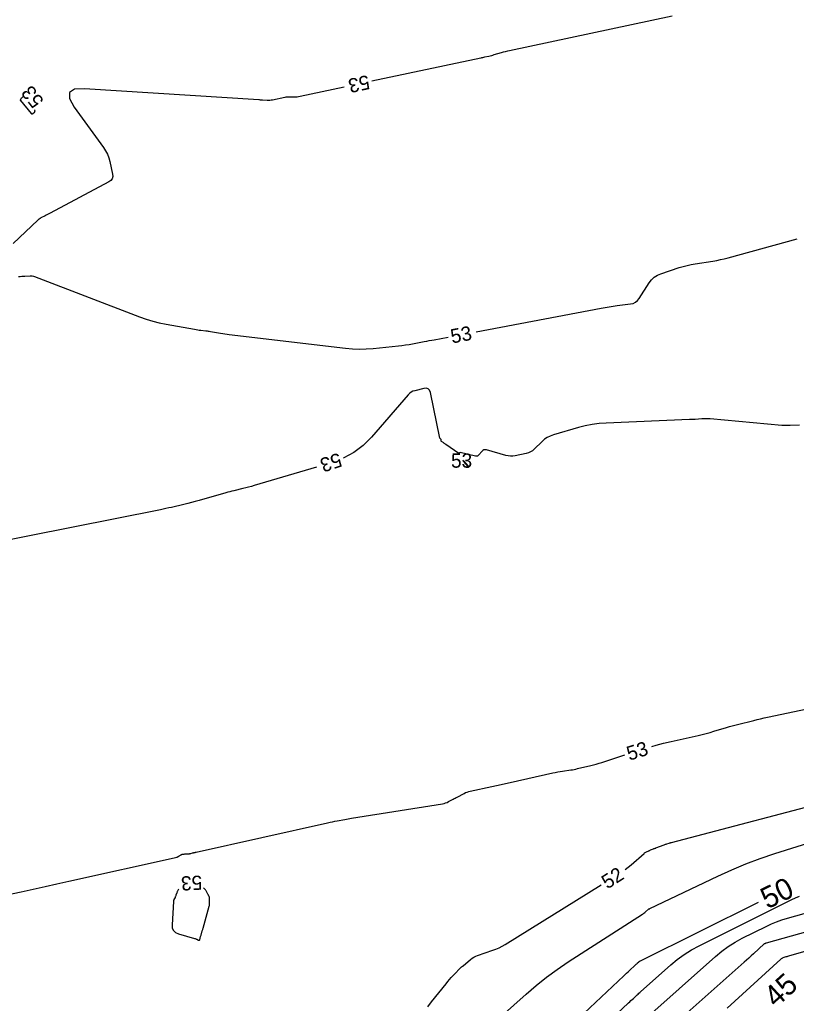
# Model space of a CAD drawing. Extents: x 2384780 to 2405861, y 547869 to 573706.
# Drawn here: x 2389896.7 to 2390006.1, y 552348.1 to 552486.4 of the extents above; entities that cross this region are included whole.
import ezdxf

# ---------------------------------------------------------------- set-up
doc = ezdxf.new("R2010")
doc.units = 0
doc.layers.add('Old_Level_60', color=7, linetype='Continuous')
doc.layers.add('Old_Level_61', color=7, linetype='Continuous')

msp = doc.modelspace()

# ---------------------------------------------------------------- linework, layer by layer
at = {"layer": 'Old_Level_60'}
for points in [[(2389988.59725, 552486.9505), (2389965.6925, 552482.06725), (2389965.39375, 552482.0005), (2389965.09625, 552481.9285), (2389964.8005, 552481.85075), (2389964.50575, 552481.76775), (2389963.5, 552481.47375), (2389963.317, 552481.42175), (2389963.13275, 552481.37275), (2389962.948, 552481.327), (2389962.7625, 552481.284), (2389962.155, 552481.149), (2389962.02475, 552481.12025), (2389961.8945, 552481.09175), (2389961.76425, 552481.0635), (2389961.63375, 552481.03575), (2389946.313, 552477.773)], [(2389942.40075, 552476.93975), (2389936.20025, 552475.61925), (2389935.99075, 552475.581), (2389935.78, 552475.5555), (2389935.568, 552475.5425), (2389935.355, 552475.54225), (2389934.657, 552475.56175), (2389934.508, 552475.56125), (2389934.3595, 552475.55225), (2389934.212, 552475.53425), (2389934.06525, 552475.5075), (2389932.32925, 552475.137), (2389932.1385, 552475.103), (2389931.94675, 552475.082), (2389931.75425, 552475.07425), (2389931.5605, 552475.0795), (2389930.926, 552475.11875), (2389930.79025, 552475.127), (2389930.65425, 552475.13575), (2389930.51825, 552475.14425), (2389930.3825, 552475.153), (2389905.84725, 552476.73475), (2389904.4555, 552476.65675), (2389903.75375, 552476.19875), (2389903.742, 552475.361), (2389904.42025, 552474.14325), (2389908.5465, 552468.46775), (2389908.845, 552468.00925), (2389909.0915, 552467.52775), (2389909.28575, 552467.02275), (2389909.428, 552466.4945), (2389909.807, 552464.73075), (2389909.83525, 552464.37725), (2389909.758, 552464.07325), (2389909.575, 552463.81825), (2389909.28625, 552463.61275), (2389901.01925, 552459.23), (2389900.84175, 552459.136), (2389900.6645, 552459.042), (2389900.487, 552458.948), (2389900.30975, 552458.854), (2389899.73025, 552458.54675), (2389899.60875, 552458.477), (2389899.49275, 552458.39975), (2389899.38225, 552458.31475), (2389899.27725, 552458.22225), (2389895.83, 552454.972)], [(2389897.25875, 552475.6915), (2389896.9425, 552475.366), (2389896.93175, 552475.354), (2389896.92225, 552475.341), (2389896.91375, 552475.327), (2389896.90675, 552475.3125), (2389896.88525, 552475.26325), (2389896.88075, 552475.25275), (2389896.876, 552475.24225), (2389896.87125, 552475.232), (2389896.86625, 552475.2215), (2389896.82675, 552475.139), (2389896.821, 552475.1215), (2389896.82025, 552475.105), (2389896.825, 552475.08875), (2389896.835, 552475.0735), (2389898.35175, 552473.256), (2389898.4125, 552473.20125), (2389898.4755, 552473.1805), (2389898.54025, 552473.19375), (2389898.60725, 552473.24125), (2389898.8285, 552473.452), (2389898.86825, 552473.4995), (2389898.8925, 552473.55175), (2389898.90125, 552473.6085), (2389898.8945, 552473.67025), (2389898.87625, 552473.7505)], [(2389897.30775, 552475.7415), (2389897.25875, 552475.6915)], [(2389960.992, 552442.54), (2389978.57725, 552445.87125), (2389979.1425, 552445.9735), (2389979.70925, 552446.06625), (2389980.27725, 552446.14925), (2389980.847, 552446.223), (2389982.71, 552446.44825), (2389983.0865, 552446.53275), (2389983.4175, 552446.68975), (2389983.703, 552446.91925), (2389983.94325, 552447.22125), (2389985.347, 552449.40675), (2389985.67625, 552449.8385), (2389986.06225, 552450.1975), (2389986.50475, 552450.4835), (2389987.00425, 552450.69675), (2389989.5745, 552451.557), (2389990.12825, 552451.72925), (2389990.68775, 552451.8775), (2389991.253, 552452.00175), (2389991.824, 552452.102), (2389994.33075, 552452.487), (2389994.86625, 552452.577), (2389995.3985, 552452.68275), (2389995.92725, 552452.8035), (2389996.453, 552452.94), (2390006.18225, 552455.61525)], [(2389896.57675, 552450.29525), (2389896.7995, 552450.32475), (2389897.02275, 552450.34825), (2389897.2465, 552450.36575), (2389897.47075, 552450.37775), (2389898.20425, 552450.4065), (2389898.36025, 552450.40475), (2389898.5135, 552450.3875), (2389898.66425, 552450.35475), (2389898.8125, 552450.30625), (2389913.62475, 552444.636), (2389914.537, 552444.31125), (2389915.4615, 552444.03075), (2389916.39825, 552443.79475), (2389917.34725, 552443.60275), (2389921.36825, 552442.888), (2389921.587, 552442.85075), (2389921.806, 552442.8165), (2389922.0255, 552442.785), (2389922.2455, 552442.75675), (2389922.965, 552442.669), (2389923.119, 552442.64925), (2389923.27275, 552442.628), (2389923.42625, 552442.60475), (2389923.5795, 552442.58), (2389925.00975, 552442.34075), (2389925.3165, 552442.2915), (2389925.624, 552442.24575), (2389925.93175, 552442.2035), (2389926.24, 552442.16525), (2389942.59225, 552440.23175), (2389943.56775, 552440.143), (2389944.54375, 552440.108), (2389945.52025, 552440.12625), (2389946.49725, 552440.19825), (2389950.045, 552440.556), (2389950.5505, 552440.6125), (2389951.05425, 552440.68), (2389951.5565, 552440.75825), (2389952.057, 552440.8475), (2389953.69, 552441.157), (2389954.04, 552441.22325), (2389954.38975, 552441.2895), (2389954.73975, 552441.35575), (2389955.08975, 552441.422), (2389957.06175, 552441.7955)], [(2390006.52175, 552429.3855), (2390005.18, 552429.3355), (2390004.89275, 552429.3295), (2390004.6055, 552429.33225), (2390004.31875, 552429.34425), (2390004.032, 552429.36525), (2389993.932, 552430.266), (2389993.6435, 552430.28625), (2389993.355, 552430.295), (2389993.06625, 552430.2925), (2389992.7775, 552430.279), (2389991.83375, 552430.21575), (2389991.6315, 552430.203), (2389991.42925, 552430.1915), (2389991.22675, 552430.18125), (2389991.02425, 552430.17225), (2389979.28525, 552429.69225), (2389978.299, 552429.62225), (2389977.32275, 552429.493), (2389976.35575, 552429.3045), (2389975.39875, 552429.057), (2389971.8675, 552428.02975), (2389971.42575, 552427.87175), (2389971.013, 552427.66425), (2389970.6295, 552427.4065), (2389970.275, 552427.099), (2389969.16525, 552426.01275), (2389968.9165, 552425.80075), (2389968.6455, 552425.6305), (2389968.3525, 552425.502), (2389968.03725, 552425.415), (2389966.4905, 552425.10175), (2389966.15975, 552425.05425), (2389965.8305, 552425.04675), (2389965.50275, 552425.07875), (2389965.1765, 552425.15025), (2389962.455, 552425.9145), (2389962.26825, 552425.943), (2389962.0975, 552425.919), (2389961.94325, 552425.84225), (2389961.80525, 552425.713), (2389961.381, 552425.20525), (2389961.28425, 552425.11375), (2389961.1755, 552425.05725), (2389961.055, 552425.03575), (2389960.9225, 552425.049), (2389958.75425, 552425.53125), (2389958.72875, 552425.5335), (2389958.70625, 552425.52875), (2389958.68625, 552425.51675), (2389958.66925, 552425.4975), (2389958.6185, 552425.423), (2389958.607, 552425.4105), (2389958.59425, 552425.4045), (2389958.58, 552425.4055), (2389958.56475, 552425.413), (2389956.745, 552426.66975), (2389956.6655, 552426.72475), (2389956.58625, 552426.78), (2389956.507, 552426.83525), (2389956.42775, 552426.89075), (2389956.12275, 552427.105), (2389956.0945, 552427.12975), (2389956.074, 552427.1585), (2389956.0615, 552427.1915), (2389956.0565, 552427.2285), (2389956.05325, 552427.35725), (2389956.05, 552427.383), (2389956.0415, 552427.40625), (2389956.028, 552427.427), (2389956.0095, 552427.44525), (2389955.94025, 552427.50025), (2389955.92675, 552427.513), (2389955.916, 552427.52725), (2389955.908, 552427.54325), (2389955.90275, 552427.561), (2389954.56425, 552433.977), (2389954.4435, 552434.31), (2389954.2455, 552434.5195), (2389953.97025, 552434.60575), (2389953.618, 552434.5685), (2389952.3415, 552434.24575), (2389952.079, 552434.1585), (2389951.83875, 552434.03525), (2389951.62075, 552433.87625), (2389951.42475, 552433.681), (2389946.26075, 552427.726)], [(2389946.26075, 552427.726), (2389945.09025, 552426.54875), (2389943.79175, 552425.56925), (2389942.36575, 552424.78775), (2389942.30175, 552424.76375)], [(2389959.10325, 552424.4145), (2389959.136, 552424.3795), (2389959.14375, 552424.371), (2389959.1515, 552424.36225), (2389959.15925, 552424.35375), (2389959.1665, 552424.34475), (2389959.85825, 552423.51875), (2389959.869, 552423.509), (2389959.88075, 552423.50425), (2389959.8935, 552423.5045), (2389959.907, 552423.50975), (2389959.95325, 552423.53475), (2389959.961, 552423.54075), (2389959.9645, 552423.54725), (2389959.96375, 552423.55475), (2389959.95875, 552423.563), (2389959.553, 552424.05875), (2389959.50925, 552424.1095), (2389959.463, 552424.1575), (2389959.414, 552424.203), (2389959.36275, 552424.246), (2389959.1235, 552424.4355), (2389959.12025, 552424.43725), (2389959.11725, 552424.43775), (2389959.11425, 552424.4365), (2389959.1115, 552424.434), (2389959.103, 552424.42325), (2389959.1015, 552424.421), (2389959.10125, 552424.41875), (2389959.10175, 552424.4165), (2389959.10325, 552424.4145)], [(2389938.50475, 552423.51275), (2389929.74625, 552420.888), (2389929.35575, 552420.7745), (2389928.9635, 552420.66725), (2389928.56975, 552420.56625), (2389928.17425, 552420.47175), (2389926.8795, 552420.17325), (2389926.60275, 552420.1075), (2389926.32675, 552420.03775), (2389926.05175, 552419.96425), (2389925.77775, 552419.887), (2389921.9995, 552418.79375), (2389921.4665, 552418.6435), (2389920.932, 552418.50075), (2389920.39525, 552418.3655), (2389919.85675, 552418.2375), (2389918.09425, 552417.8315), (2389917.71625, 552417.746), (2389917.33775, 552417.66325), (2389916.9585, 552417.5835), (2389916.57875, 552417.50625), (2389891.6995, 552412.55325)], [(2389985.728, 552384.21475), (2389986.33075, 552384.386), (2389987.38, 552384.6575), (2389988.436, 552384.9035), (2389992.264, 552385.747), (2389992.82075, 552385.87575), (2389993.37475, 552386.016), (2389993.9255, 552386.1675), (2389994.47325, 552386.33075), (2389996.2575, 552386.8825), (2389996.6405, 552386.998), (2389997.02525, 552387.10775), (2389997.4115, 552387.212), (2389997.79925, 552387.3105), (2390000.06975, 552387.86975), (2390000.55675, 552387.9875), (2390001.04475, 552388.1005), (2390001.534, 552388.209), (2390002.024, 552388.313), (2390007.60775, 552389.471)], [(2389889.07575, 552362.087), (2389896.93925, 552363.757), (2389898.6235, 552364.11725), (2389900.307, 552364.4825), (2389901.9895, 552364.85225), (2389903.67075, 552365.227), (2389918.8875, 552368.64075), (2389918.9315, 552368.6525), (2389918.97375, 552368.66825), (2389919.0145, 552368.68775), (2389919.05375, 552368.711), (2389919.17925, 552368.79275), (2389919.20625, 552368.81025), (2389919.233, 552368.82775), (2389919.26, 552368.84525), (2389919.28675, 552368.863), (2389919.456, 552368.97325), (2389919.493, 552368.9945), (2389919.53175, 552369.01125), (2389919.57225, 552369.02325), (2389919.6145, 552369.0305), (2389919.91625, 552369.066), (2389919.981, 552369.073), (2389920.046, 552369.07875), (2389920.11075, 552369.0835), (2389920.17575, 552369.08675), (2389920.57125, 552369.104), (2389920.6415, 552369.10925), (2389920.71075, 552369.11925), (2389920.779, 552369.1335), (2389920.84675, 552369.1525), (2389921.0665, 552369.222), (2389921.11375, 552369.236), (2389921.1615, 552369.248), (2389921.2095, 552369.2585), (2389921.258, 552369.267), (2389921.42725, 552369.29375), (2389921.46325, 552369.29975), (2389921.4995, 552369.30625), (2389921.5355, 552369.3135), (2389921.57125, 552369.32125), (2389940.09425, 552373.473), (2389940.4235, 552373.54525), (2389940.7535, 552373.614), (2389941.084, 552373.67975), (2389941.41525, 552373.742), (2389942.4985, 552373.9405), (2389942.73075, 552373.98225), (2389942.96325, 552374.02275), (2389943.196, 552374.062), (2389943.429, 552374.09975), (2389956.2625, 552376.148), (2389956.482, 552376.1925), (2389956.69525, 552376.25475), (2389956.90275, 552376.33525), (2389957.10375, 552376.4335), (2389957.75125, 552376.78375), (2389957.89, 552376.8585), (2389958.029, 552376.933), (2389958.16825, 552377.00725), (2389958.30775, 552377.08075), (2389959.28825, 552377.5975), (2389959.50125, 552377.7005), (2389959.71975, 552377.7885), (2389959.9435, 552377.86125), (2389960.173, 552377.91875), (2389963.2005, 552378.5695), (2389963.849, 552378.7095), (2389964.4975, 552378.8505), (2389965.1455, 552378.993), (2389965.7935, 552379.1365), (2389971.7895, 552380.47), (2389972.13375, 552380.54325), (2389972.47925, 552380.61025), (2389972.82575, 552380.671), (2389973.1735, 552380.72525), (2389974.31125, 552380.89275), (2389974.5545, 552380.93125), (2389974.79675, 552380.97525), (2389975.038, 552381.02475), (2389975.278, 552381.07975), (2389977.12475, 552381.5245), (2389977.5195, 552381.6235), (2389977.912, 552381.73), (2389978.30225, 552381.84425), (2389978.6905, 552381.96575), (2389981.914, 552383.01025)], [(2389981.97475, 552366.88425), (2389982.3865, 552367.2035), (2389982.81575, 552367.56575), (2389984.6285, 552369.162), (2389984.70925, 552369.228), (2389984.7945, 552369.28725), (2389984.884, 552369.34), (2389984.9775, 552369.38575), (2389985.29075, 552369.525), (2389985.35775, 552369.5545), (2389985.42525, 552369.584), (2389985.4925, 552369.613), (2389985.56025, 552369.64175), (2389985.95575, 552369.80875), (2389985.99025, 552369.8225), (2389986.025, 552369.83525), (2389986.06025, 552369.8465), (2389986.09575, 552369.857), (2389986.21275, 552369.8885), (2389986.23775, 552369.8955), (2389986.2625, 552369.90325), (2389986.287, 552369.91175), (2389986.31125, 552369.92075), (2389987.4395, 552370.36), (2389987.541, 552370.39875), (2389987.643, 552370.43575), (2389987.7455, 552370.4715), (2389987.84875, 552370.5055), (2389988.1865, 552370.6145), (2389988.259, 552370.63725), (2389988.33175, 552370.65925), (2389988.405, 552370.68), (2389988.47825, 552370.69975), (2390012.75875, 552377.06075)], [(2389961.524, 552343.5285), (2389968.01525, 552349.3605), (2389969.429, 552350.58025), (2389970.8885, 552351.74), (2389972.39375, 552352.83975), (2389973.9445, 552353.8795), (2389984.4085, 552360.59375), (2389984.517, 552360.667), (2389984.622, 552360.7445), (2389984.72325, 552360.82675), (2389984.82125, 552360.9135), (2389985.238, 552361.29975), (2389985.2545, 552361.31325), (2389985.272, 552361.32475), (2389985.291, 552361.33425), (2389985.311, 552361.3415), (2389985.37875, 552361.36175), (2389985.39325, 552361.36625), (2389985.40725, 552361.3715), (2389985.42125, 552361.37725), (2389985.435, 552361.3835), (2389995.014, 552365.9645), (2389996.9755, 552366.86025), (2389998.96525, 552367.68475), (2390000.98275, 552368.438), (2390003.0285, 552369.12), (2390010.0565, 552371.32525)], [(2389984.44275, 552345.56175), (2389994.68475, 552354.667), (2389995.56475, 552355.399), (2389996.48725, 552356.068), (2389997.45225, 552356.674), (2389998.45975, 552357.217), (2390001.82025, 552358.8885), (2390002.54725, 552359.22875), (2390003.288, 552359.5335), (2390004.04225, 552359.8025), (2390004.81025, 552360.03575), (2390008.686, 552361.11375), (2390009.50925, 552361.36375), (2390010.31825, 552361.65125), (2390011.1125, 552361.977), (2390011.8925, 552362.34025), (2390017.1815, 552364.95675), (2390018.32275, 552365.4985), (2390018.53075, 552365.58925)], [(2389919.101, 552357.833), (2389921.3575, 552357.20075), (2389921.44075, 552357.17525), (2389921.52225, 552357.146), (2389921.6025, 552357.11275), (2389921.681, 552357.07575), (2389921.9355, 552356.94825), (2389921.9855, 552356.93175), (2389922.02625, 552356.9365), (2389922.0575, 552356.96275), (2389922.07975, 552357.0105), (2389922.216, 552357.4625), (2389922.245, 552357.5595), (2389922.27375, 552357.6565), (2389922.30175, 552357.7535), (2389922.3295, 552357.851), (2389922.44975, 552358.27675), (2389922.47575, 552358.368), (2389922.50125, 552358.45925), (2389922.527, 552358.5505), (2389922.5525, 552358.64175), (2389923.42275, 552361.7465), (2389923.439, 552361.81225), (2389923.4515, 552361.8785), (2389923.46, 552361.9455), (2389923.4645, 552362.01325), (2389923.4725, 552362.235), (2389923.474, 552362.2825), (2389923.47525, 552362.33), (2389923.476, 552362.37775), (2389923.47625, 552362.42525), (2389923.477, 552362.787), (2389923.4735, 552362.85575), (2389923.4625, 552362.92275), (2389923.44425, 552362.98825), (2389923.4185, 552363.05225), (2389923.32275, 552363.25825), (2389923.30175, 552363.30225), (2389923.28025, 552363.34575), (2389923.25775, 552363.389), (2389923.2345, 552363.43175), (2389922.9795, 552363.89375), (2389922.944, 552363.95275), (2389922.904, 552364.0085), (2389922.85975, 552364.06075), (2389922.81125, 552364.10975), (2389922.64575, 552364.26425), (2389922.61225, 552364.29475)], [(2389961.203, 552354.801), (2389963.336, 552355.5205), (2389963.787, 552355.68725), (2389964.2265, 552355.87875), (2389964.654, 552356.0955), (2389965.06975, 552356.33725), (2389978.60375, 552364.73325)], [(2389919.11225, 552364.12975), (2389919.0115, 552363.9445), (2389918.97025, 552363.86525), (2389918.93225, 552363.7845), (2389918.8975, 552363.7025), (2389918.86575, 552363.61875), (2389918.7385, 552363.26225), (2389918.71, 552363.18625), (2389918.67875, 552363.1115), (2389918.64475, 552363.038), (2389918.608, 552362.96575), (2389918.44825, 552362.66375), (2389918.41775, 552362.598), (2389918.395, 552362.53025), (2389918.3795, 552362.46025), (2389918.37175, 552362.38825), (2389918.1895, 552359.10675), (2389918.2255, 552358.65125), (2389918.3895, 552358.287), (2389918.68125, 552358.01425), (2389919.101, 552357.833)], [(2389965.614, 552332.2915), (2389982.4615, 552348.13575), (2389982.62675, 552348.29125), (2389982.79225, 552348.44675), (2389982.9575, 552348.60225), (2389983.123, 552348.75775), (2389983.66325, 552349.26575), (2389983.77925, 552349.37425), (2389983.89625, 552349.482), (2389984.01375, 552349.58875), (2389984.13225, 552349.69475), (2389988.38, 552353.47125), (2389989.313, 552354.247), (2389990.29075, 552354.95625), (2389991.31375, 552355.59875), (2389992.38175, 552356.1745), (2390005.414, 552362.65575), (2390005.95375, 552362.9085), (2390006.5035, 552363.13475)], [(2390008.859, 552358.47525), (2390001.80825, 552356.51425), (2390001.78125, 552356.5065), (2390001.7545, 552356.4985), (2390001.72775, 552356.49), (2390001.70125, 552356.48125), (2390001.61475, 552356.45175), (2390001.59675, 552356.4445), (2390001.5795, 552356.4355), (2390001.5635, 552356.425), (2390001.54875, 552356.41275), (2390000.0285, 552355.02425), (2389999.70225, 552354.7275), (2389999.375, 552354.4315), (2389999.047, 552354.13675), (2389998.71775, 552353.84325), (2389984.8095, 552341.4785)], [(2390009.425, 552355.94625), (2390005.088, 552354.73975), (2390004.96225, 552354.704), (2390004.837, 552354.66625), (2390004.71225, 552354.62675), (2390004.58825, 552354.5855), (2390004.18375, 552354.44775), (2390004.0995, 552354.41425), (2390004.01975, 552354.37275), (2390003.945, 552354.323), (2390003.875, 552354.26525), (2389996.318, 552347.3635)], [(2389954.20725, 552347.58), (2389954.7315, 552348.263), (2389956.7545, 552350.8225), (2389956.993, 552351.11675), (2389957.23875, 552351.4045), (2389957.4915, 552351.68625), (2389957.7515, 552351.9615), (2389958.94775, 552353.19675), (2389958.96525, 552353.21375), (2389958.98375, 552353.2295), (2389959.003, 552353.244), (2389959.0235, 552353.25725), (2389959.09175, 552353.29875), (2389959.10625, 552353.308), (2389959.12025, 552353.31775), (2389959.134, 552353.328), (2389959.14725, 552353.339), (2389960.19525, 552354.2305), (2389960.4265, 552354.4095), (2389960.67175, 552354.56425), (2389960.9305, 552354.69475), (2389961.203, 552354.801)]]:
    msp.add_lwpolyline(points, dxfattribs=at)
at = {"layer": 'Old_Level_61'}
msp.add_lwpolyline([(2389975.38975, 552345.913), (2389981.7755, 552351.9185), (2389981.978, 552352.109), (2389982.18075, 552352.2995), (2389982.38325, 552352.49), (2389982.58575, 552352.68025), (2389983.39375, 552353.44025), (2389983.4625, 552353.5045), (2389983.5315, 552353.56825), (2389983.60125, 552353.63125), (2389983.67125, 552353.694), (2389983.90075, 552353.89825), (2389983.95125, 552353.94), (2389984.004, 552353.9785), (2389984.05925, 552354.013), (2389984.117, 552354.04425), (2390000.75325, 552362.318)], dxfattribs=at)

# ---------------------------------------------------------------- texts
at = {"layer": 'Old_Level_60'}
for s, rotation, p in [('53', 192.0221306, (2389945.758, 552478.67725)), ('53', 128.2291806, (2389900.2375, 552475.02725)), ('53', 10.7265028, (2389957.59625, 552440.879)), ('53', 198.2358722, (2389941.6705, 552425.5515)), ('53', 17.5269667, (2389982.54875, 552382.1775)), ('52', 32.5416389, (2389979.46725, 552364.06775)), ('53', 182.7022944, (2389922.3885, 552366.05225))]:
    msp.add_text(s, height=2, rotation=rotation, dxfattribs=at).set_placement(p)
msp.add_text('53', height=2, dxfattribs=at).set_placement((2389957.45775, 552423.4145))
at = {"layer": 'Old_Level_61'}
for s, rotation, p in [('50', 26.4428389, (2390001.9925, 552361.259)), ('45', 42.4050611, (2390003.19825, 552347.34375))]:
    msp.add_text(s, height=3, rotation=rotation, dxfattribs=at).set_placement(p)

doc.saveas('drawing.dxf')
